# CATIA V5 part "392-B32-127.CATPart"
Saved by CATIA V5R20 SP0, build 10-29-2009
Part number: 392-B32-127
Definition: NONE
Nomenclature: 392-B32-127
Source: Unknown
Description: 392-B32-127
Bounding box of the stored display mesh (mm): x 0 to 127, y -15.619 to 15.619, z -15.5 to 15.5
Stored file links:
  C:\Users\Utente\Desktop\IO LAVORO\3D X SITO CF\X SITO\3D files 392B\392-B32-127.CATPart
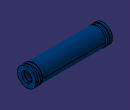
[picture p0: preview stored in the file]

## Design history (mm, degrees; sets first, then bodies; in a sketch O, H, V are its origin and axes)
Body1 "392-B32-127" (main body)
  Solid1: solid without history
